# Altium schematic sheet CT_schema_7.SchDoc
size 287 x 160 mm
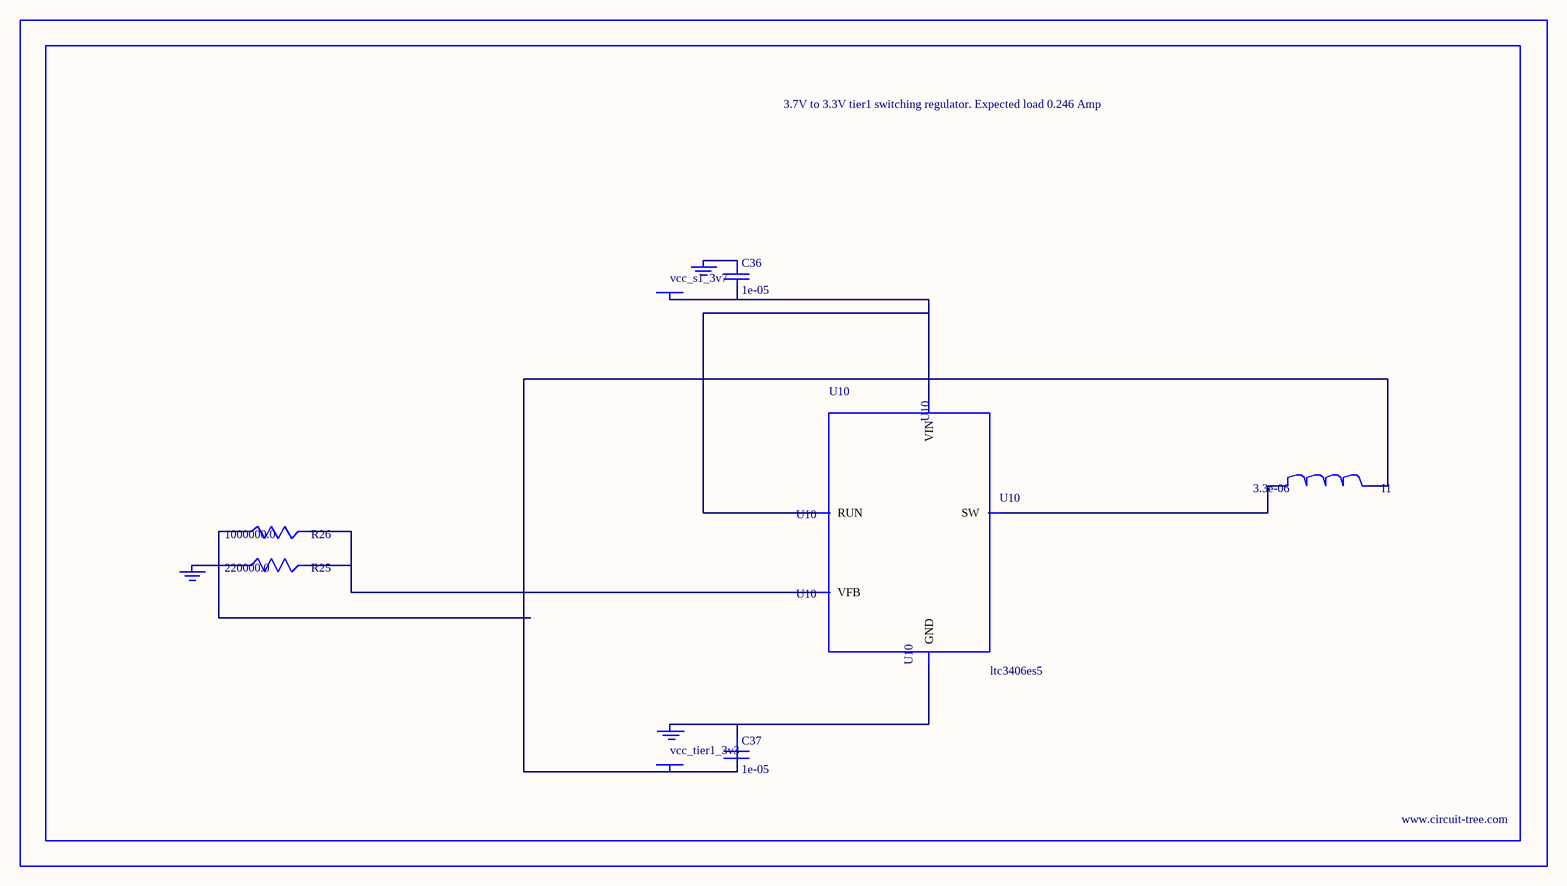
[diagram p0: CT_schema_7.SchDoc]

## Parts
BORDER6  (no value)
C36  1e-05  [C0805]
C37  1e-05  [C0805]
GND_INSTANCE_6_0  (no value)
GND_INSTANCE_6_1  (no value)
GND_INSTANCE_6_2  (no value)
I1  3.3e-06  [L0806]
POWER_INSTANCE_6_0  vcc_tier1_3v3
POWER_INSTANCE_6_1  vcc_s1_3v7
R25  220000.0  [R0603]
R26  1000000.0  [R0603]
U10  ltc3406es5  [TSOT-23-5]

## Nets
NetC36_1: C36.1 GND_INSTANCE_6_1.0(GND)
NetC36_2: C36.2 POWER_INSTANCE_6_1.0(PWR) U10.1(RUN) U10.4(VIN)
NetC37_1: C37.1 GND_INSTANCE_6_0.0(GND) U10.2(GND)
NetC37_2: C37.2 I1.2 POWER_INSTANCE_6_0.0(PWR) R26.1
NetGND_INSTANCE_6_2_0: GND_INSTANCE_6_2.0(GND) R25.1
NetI1_1: I1.1 U10.3(SW)
NetR25_2: R25.2 R26.2 U10.5(VFB)

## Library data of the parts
BORDER6 = BORDER_PAGE6
C36 C37 = C0805C106K8RACTU
GND_INSTANCE_6_0-GND_INSTANCE_6_2 = GND
I1 = L0806C3R3MDWIT
POWER_INSTANCE_6_0 POWER_INSTANCE_6_1 = PWR
R25 = RC0603JR-07220KL
R26 = RC0603JR-071ML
